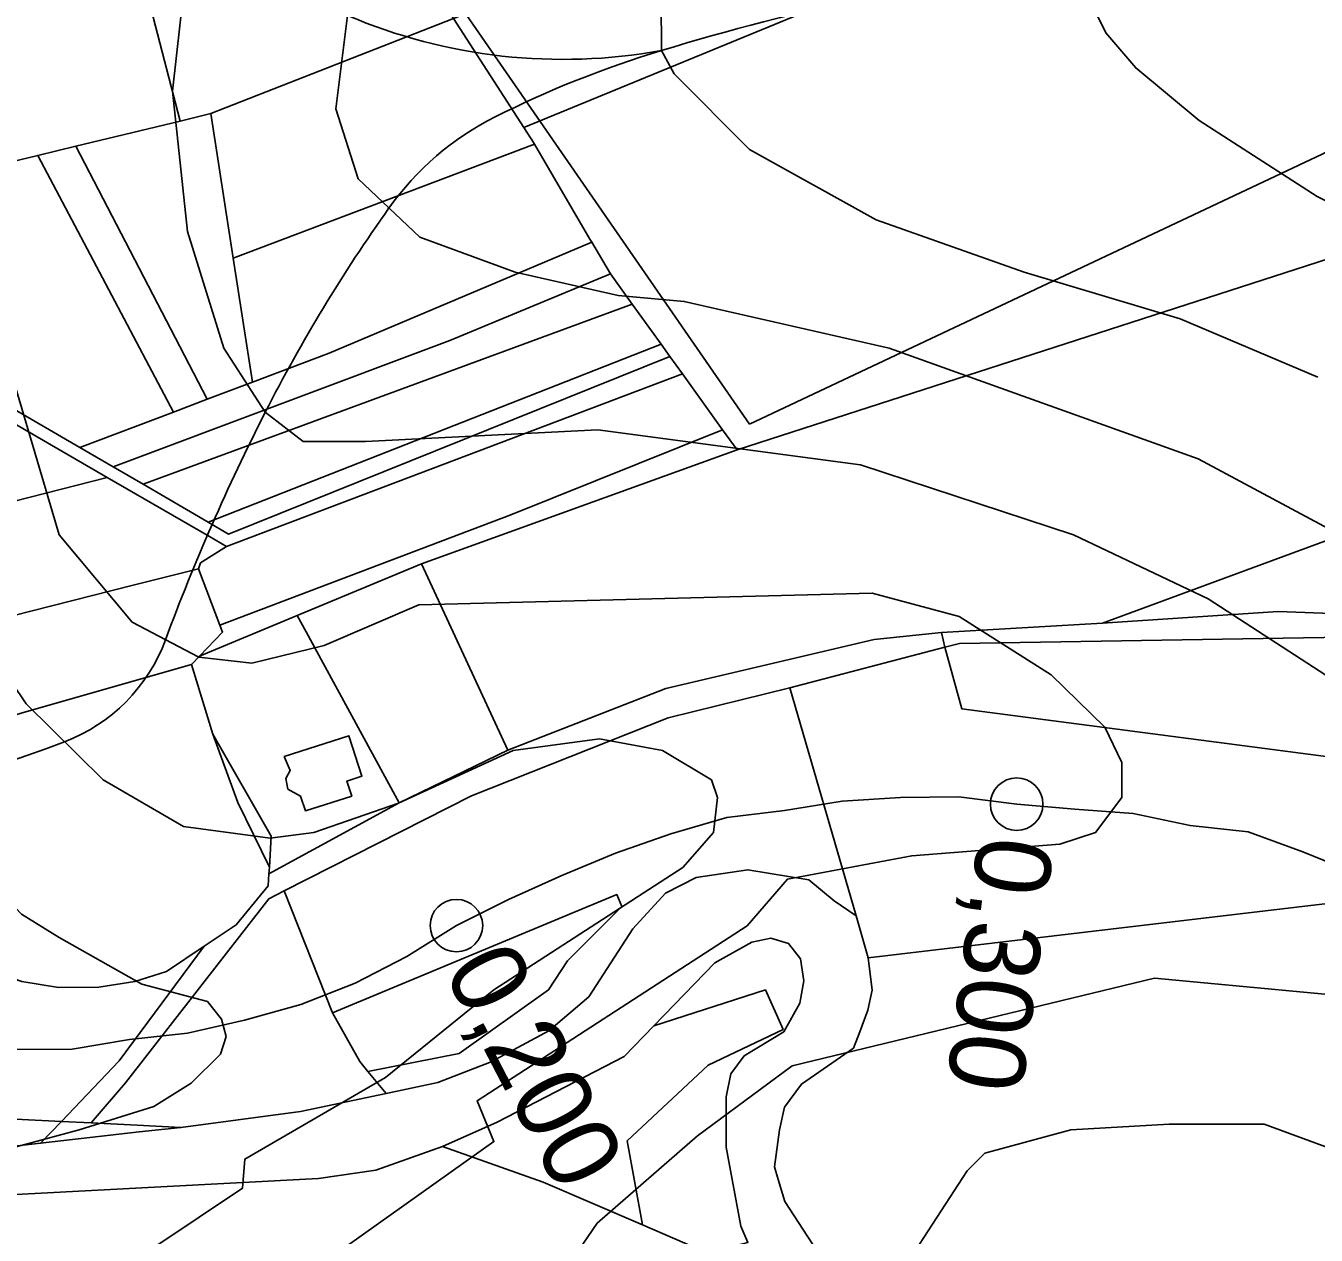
# Model space of a CAD drawing. Extents: x -510989 to -501240, y -1184665 to -1176098.
# Drawn here: x -509352 to -509130.9, y -1179477 to -1179269.8 of the extents above; entities that cross this region are included whole.
import ezdxf

# ---------------------------------------------------------------- set-up
doc = ezdxf.new("R2010")
doc.units = 0
for name, color, linetype in [('NAVRH_rozvodnice', 7, 'Continuous'), ('orna_puda', 7, 'Continuous'), ('ostatni_plocha_x_manipulacni_plocha', 7, 'Continuous'), ('ostatni_plocha_x_neplodna_puda', 7, 'Continuous'), ('ostatni_plocha_x_ostatni_komunikace', 7, 'Continuous'), ('ostatni_plocha_x_silnice', 7, 'Continuous'), ('STAV_systematicke_odvodneni', 7, 'Continuous'), ('trasovani_toku', 7, 'Continuous'), ('trvaly_travni_porost', 7, 'Continuous'), ('vodni_plocha_x_zamokrena_plocha', 7, 'Continuous'), ('vrstevnice_01', 7, 'Continuous'), ('vrstevnice_02', 7, 'Continuous'), ('zahrada', 7, 'Continuous'), ('zastavena_plocha_a_nadvori', 7, 'Continuous')]:
    doc.layers.add(name, color=color, linetype=linetype)

msp = doc.modelspace()

# ---------------------------------------------------------------- linework, layer by layer
at = {"layer": 'NAVRH_rozvodnice'}
for centre, radius, start, end in [((-509121.63, -1179673.51), 417.56, 96.9373, 106.9113), ((-509260, -1179181.33), 94.2, 246.9349, 280.341), ((-509190.44, -1179447.18), 181.01, 106.9113, 116.6322), ((-509249.32, -1179329.77), 49.66, 116.6322, 144.5973), ((-509061.79, -1179463.05), 279.73, 144.5973, 152.9866), ((-508984.09, -1179502.67), 366.95, 152.9866, 159.64), ((-509356.13, -1179364.6), 29.89, 291.0285, 339.64), ((-509414.25, -1179213.41), 191.87, 258.3329, 291.0285), ((-509229.64, -1179301.75), 244.6, 204.0197, 246.4643)]:
    msp.add_arc(centre, radius, start, end, dxfattribs=at)
at = {"layer": 'orna_puda'}
for points in [[(-509076.81, -1179197.19), (-509210.24, -1179254.85), (-509207.03, -1179262.64), (-509266.7, -1179287.2), (-509278.76, -1179268.53), (-509180.65, -1179229.56), (-509081.74, -1179187.06)], [(-509292.36, -1179257.49), (-509286.98, -1179255.81), (-509278.76, -1179268.53), (-509320.36, -1179284.83), (-509325.57, -1179286.09), (-509330.63, -1179266.76), (-509326.53, -1179266.76), (-509307.98, -1179262.36)], [(-509320.36, -1179284.83), (-509278.76, -1179268.53), (-509266.7, -1179287.2), (-509264.93, -1179289.94), (-509264.87, -1179290.04), (-509316.49, -1179309.62)], [(-509264.87, -1179290.04), (-509255.35, -1179306.33), (-509255.04, -1179306.86), (-509300.06, -1179325.87), (-509313.18, -1179330.83), (-509316.49, -1179309.62)], [(-509255.04, -1179306.86), (-509251.86, -1179312.29), (-509279.35, -1179323.71), (-509337.05, -1179345.38), (-509342.8, -1179342.04), (-509326.75, -1179335.97), (-509320.94, -1179333.77), (-509313.18, -1179330.83), (-509300.06, -1179325.87)], [(-509251.86, -1179312.29), (-509248.12, -1179317.48), (-509331.95, -1179348.35), (-509337.05, -1179345.38), (-509279.35, -1179323.71)], [(-509248.12, -1179317.48), (-509243.17, -1179324.34), (-509320.81, -1179354.82), (-509331.95, -1179348.35)], [(-509239.5, -1179329.43), (-509232.61, -1179338.99), (-509268.93, -1179353.6), (-509318.79, -1179372.47), (-509322.43, -1179362.81), (-509322.09, -1179361.81), (-509317.63, -1179359.01)], [(-509250.74, -1179418.66), (-509249.88, -1179420.73), (-509259.22, -1179430.01), (-509262.44, -1179435.01), (-509277.78, -1179445.9), (-509293.43, -1179448.96), (-509294.82, -1179447.27), (-509299.51, -1179438.92)], [(-509244.42, -1179441.17), (-509225.29, -1179435), (-509222.26, -1179441.78), (-509235.07, -1179447.92), (-509248.95, -1179460.87), (-509246.37, -1179475.26), (-509263.39, -1179467.95), (-509280.62, -1179461.86), (-509271.28, -1179457.69), (-509249.49, -1179446.42)]]:
    msp.add_lwpolyline(points, close=True, dxfattribs=at)
msp.add_lwpolyline([(-509096.81, -1179299.39), (-509230.1, -1179342.45), (-509232.61, -1179338.99), (-509239.5, -1179329.43), (-509241.64, -1179326.46), (-509243.17, -1179324.34), (-509248.12, -1179317.48), (-509251.86, -1179312.29), (-509255.04, -1179306.86), (-509255.35, -1179306.33), (-509264.87, -1179290.04), (-509264.93, -1179289.94), (-509266.7, -1179287.2), (-509207.03, -1179262.64), (-509210.24, -1179254.85), (-509076.81, -1179197.19)], dxfattribs=at)
at = {"layer": 'ostatni_plocha_x_manipulacni_plocha'}
for points in [[(-509284.22, -1179362), (-509269.44, -1179393.92), (-509288.08, -1179402.95), (-509301.07, -1179379.03), (-509304, -1179373.63), (-509305.51, -1179370.84)], [(-509305.51, -1179370.84), (-509304, -1179373.63), (-509301.07, -1179379.03), (-509288.08, -1179402.95), (-509310.37, -1179415.09), (-509310.3, -1179413.94), (-509309.98, -1179408.66), (-509320.02, -1179391.16), (-509323.65, -1179379.22), (-509322.28, -1179377.8)], [(-509320.02, -1179391.16), (-509309.98, -1179408.66), (-509310.3, -1179413.94), (-509315.71, -1179402.9)], [(-509307.77, -1179394.99), (-509306.72, -1179397.4), (-509307.49, -1179398.79), (-509307.11, -1179400.57), (-509304.94, -1179401.79), (-509304.13, -1179404.31), (-509296.19, -1179401.77), (-509297.01, -1179399.2), (-509294.44, -1179398.37), (-509296.66, -1179391.44)], [(-509367.47, -1179426.62), (-509357.46, -1179430.05), (-509357.1, -1179432.06), (-509352.71, -1179433.56), (-509346.44, -1179434.6), (-509339.56, -1179434.54), (-509333.34, -1179433.54), (-509327.93, -1179431.87), (-509321.45, -1179427.53), (-509336.03, -1179447.17), (-509345.95, -1179457.53), (-509361.74, -1179456.77), (-509362.16, -1179452.72), (-509360.92, -1179452.7), (-509354.81, -1179452.62), (-509354.89, -1179447.24), (-509354.92, -1179445.17), (-509358.59, -1179432.54), (-509361.5, -1179429.63), (-509366.25, -1179427.89), (-509367.37, -1179427.48)], [(-509224.33, -1179426.12), (-509221.31, -1179427.02), (-509219.26, -1179429.7), (-509218.7, -1179433.42), (-509219.38, -1179437.3), (-509222.1, -1179442.16), (-509228.9, -1179446.3), (-509231.18, -1179449.41), (-509231.98, -1179453.34), (-509231.99, -1179461.98), (-509229.51, -1179475.49), (-509228.28, -1179478.29), (-509235.24, -1179480.05), (-509246.37, -1179475.26), (-509248.95, -1179460.87), (-509235.07, -1179447.92), (-509222.26, -1179441.78), (-509225.29, -1179435), (-509244.42, -1179441.17), (-509233.94, -1179430.34), (-509227.6, -1179426.81)], [(-509345.95, -1179457.53), (-509349.53, -1179461.27), (-509366.43, -1179463.21), (-509383.93, -1179465.38), (-509391.81, -1179464.7), (-509397.83, -1179462.93), (-509401.32, -1179461.12), (-509404.1, -1179458.33), (-509400.34, -1179458.29), (-509395.73, -1179462), (-509391.16, -1179463.21), (-509390.99, -1179461.48), (-509382.86, -1179462.27), (-509379.84, -1179458.92), (-509373.07, -1179459.94), (-509361.54, -1179458.76), (-509361.74, -1179456.77)], [(-509340.86, -1179457.78), (-509332.96, -1179458.16), (-509325.47, -1179458.59), (-509332.63, -1179459.34), (-509349.53, -1179461.27), (-509345.95, -1179457.53)]]:
    msp.add_lwpolyline(points, close=True, dxfattribs=at)
at = {"layer": 'ostatni_plocha_x_neplodna_puda'}
for points in [[(-509232.61, -1179338.99), (-509230.1, -1179342.45), (-509284.22, -1179362), (-509305.51, -1179370.84), (-509322.28, -1179377.8), (-509318.32, -1179373.69), (-509318.79, -1179372.47), (-509268.93, -1179353.6)], [(-509110.64, -1179351.17), (-509067.16, -1179352.61), (-509072.25, -1179357.15), (-509083.67, -1179365.13), (-509102.55, -1179371.49), (-509137.38, -1179370.15), (-509167.51, -1179372.13)], [(-509094.91, -1179374.01), (-509094.69, -1179399.52), (-509191.61, -1179386.85), (-509194.51, -1179376.28), (-509192, -1179375.62)]]:
    msp.add_lwpolyline(points, close=True, dxfattribs=at)
msp.add_lwpolyline([(-509360.79, -1179477.49), (-509360.83, -1179475.33), (-509358.84, -1179474.32), (-509358.81, -1179473.38), (-509359.4, -1179472.4), (-509360.89, -1179472.2), (-509361.37, -1179470.48), (-509329.98, -1179468.83), (-509301.88, -1179467.35), (-509292.06, -1179465.9), (-509280.62, -1179461.86), (-509263.39, -1179467.95), (-509246.37, -1179475.26), (-509235.24, -1179480.05)], dxfattribs=at)
at = {"layer": 'ostatni_plocha_x_ostatni_komunikace'}
for points in [[(-509404.18, -1179303.47), (-509399.56, -1179303.43), (-509398.12, -1179304.81), (-509383.51, -1179308.94), (-509370.93, -1179321.28), (-509354.95, -1179334.98), (-509342.8, -1179342.04), (-509337.05, -1179345.38), (-509331.95, -1179348.35), (-509320.81, -1179354.82), (-509317.29, -1179356.87), (-509241.64, -1179326.46), (-509239.5, -1179329.43), (-509317.63, -1179359.01), (-509320.57, -1179357.31), (-509338.08, -1179347.17), (-509354.32, -1179337.76), (-509358.69, -1179334.22), (-509369.88, -1179325.14), (-509378.6, -1179318.06), (-509378.65, -1179318.01), (-509384.73, -1179313.61), (-509395.33, -1179308.26), (-509401.56, -1179305.12)], [(-509243.17, -1179324.34), (-509241.64, -1179326.46), (-509317.29, -1179356.87), (-509320.81, -1179354.82)], [(-509206.62, -1179374.96), (-509195.12, -1179373.77), (-509194.51, -1179376.28), (-509221.07, -1179383.22), (-509241.96, -1179388.37), (-509275.63, -1179401.72), (-509307.75, -1179418.02), (-509310.41, -1179419.38), (-509334.98, -1179450.92), (-509340.86, -1179457.78), (-509345.95, -1179457.53), (-509336.03, -1179447.17), (-509321.45, -1179427.53), (-509315.98, -1179423.87), (-509310.5, -1179417.16), (-509310.37, -1179415.09), (-509288.08, -1179402.95), (-509269.44, -1179393.92), (-509242.33, -1179383.33)]]:
    msp.add_lwpolyline(points, close=True, dxfattribs=at)
msp.add_lwpolyline([(-509094.91, -1179374.01), (-509192, -1179375.62), (-509194.51, -1179376.28), (-509195.12, -1179373.77), (-509167.51, -1179372.13), (-509137.38, -1179370.15), (-509102.55, -1179371.49)], dxfattribs=at)
at = {"layer": 'ostatni_plocha_x_silnice'}
for points in [[(-509366.43, -1179463.21), (-509349.53, -1179461.27), (-509332.63, -1179459.34), (-509325.47, -1179458.59), (-509304.99, -1179455.84), (-509290.31, -1179452.73), (-509281.42, -1179450.86), (-509272.27, -1179447.34), (-509262.38, -1179442.04), (-509255.55, -1179436.19), (-509248, -1179424.52), (-509242.43, -1179418.45), (-509237.14, -1179415.74), (-509228.29, -1179414.41), (-509217.86, -1179416.14), (-509213.49, -1179419.71), (-509209.73, -1179422.33), (-509207.65, -1179429.48), (-509206.99, -1179435.04), (-509207.7, -1179438.47), (-509209.12, -1179442.17), (-509210.19, -1179444.96), (-509219.11, -1179451.13), (-509222.02, -1179455.07), (-509222.84, -1179458.99), (-509223.72, -1179465.32), (-509223.08, -1179467.47), (-509221.97, -1179471.24), (-509202.14, -1179501.69)], [(-509228.28, -1179478.29), (-509229.51, -1179475.49), (-509231.99, -1179461.98), (-509231.98, -1179453.34), (-509231.18, -1179449.41), (-509228.9, -1179446.3), (-509222.1, -1179442.16), (-509219.38, -1179437.3), (-509218.7, -1179433.42), (-509219.26, -1179429.7), (-509221.31, -1179427.02), (-509224.33, -1179426.12), (-509227.6, -1179426.81), (-509233.94, -1179430.34), (-509244.42, -1179441.17), (-509249.49, -1179446.42), (-509271.28, -1179457.69), (-509280.62, -1179461.86), (-509292.06, -1179465.9), (-509301.88, -1179467.35), (-509329.98, -1179468.83), (-509361.37, -1179470.48)]]:
    msp.add_lwpolyline(points, dxfattribs=at)
at = {"layer": 'STAV_systematicke_odvodneni'}
for p, q in [((-509228.03, -1179338.07), (-509023.75, -1179241.74)), ((-509288.68, -1179250.26), (-509228.03, -1179338.07))]:
    msp.add_line(p, q, dxfattribs=at)
at = {"layer": 'trasovani_toku'}
for p, q in [((-509212.11, -1179402.67), (-509202.13, -1179402.04)), ((-509202.13, -1179402.04), (-509192.13, -1179401.91)), ((-509192.13, -1179401.91), (-509182.21, -1179403.17)), ((-509231.9, -1179405.48), (-509221.98, -1179404.27)), ((-509221.98, -1179404.27), (-509212.11, -1179402.67)), ((-509182.21, -1179403.17), (-509172.25, -1179404.05)), ((-509172.25, -1179404.05), (-509162.27, -1179404.78)), ((-509241.5, -1179408.28), (-509231.9, -1179405.48)), ((-509162.27, -1179404.78), (-509152.49, -1179406.84)), ((-509152.49, -1179406.84), (-509142.54, -1179407.9)), ((-509250.95, -1179411.55), (-509241.5, -1179408.28)), ((-509142.54, -1179407.9), (-509133.15, -1179411.34)), ((-509260.19, -1179415.38), (-509250.95, -1179411.55)), ((-509133.15, -1179411.34), (-509123.9, -1179415.13)), ((-509269.29, -1179419.52), (-509260.19, -1179415.38)), ((-509278.24, -1179423.98), (-509269.29, -1179419.52)), ((-509286.72, -1179429.28), (-509278.24, -1179423.98)), ((-509295.62, -1179433.85), (-509286.72, -1179429.28)), ((-509304.93, -1179437.51), (-509295.62, -1179433.85)), ((-509314.56, -1179440.21), (-509304.93, -1179437.51)), ((-509324.31, -1179442.41), (-509314.56, -1179440.21)), ((-509344.11, -1179445.17), (-509334.25, -1179443.48)), ((-509334.25, -1179443.48), (-509324.31, -1179442.41)), ((-509354.11, -1179445.22), (-509344.11, -1179445.17))]:
    msp.add_line(p, q, dxfattribs=at)
for centre in [(-509182.21, -1179403.17), (-509278.24, -1179423.98)]:
    msp.add_circle(centre, 4.5, dxfattribs=at)
at = {"layer": 'trvaly_travni_porost'}
for points in [[(-508978.56, -1179251.27), (-508978.81, -1179257.56), (-508989.24, -1179271.89), (-509002.08, -1179283.15), (-509013.85, -1179296.97), (-509031.08, -1179317.2), (-509067.16, -1179352.61), (-509110.64, -1179351.17), (-509167.51, -1179372.13), (-509195.12, -1179373.77), (-509206.62, -1179374.96), (-509242.33, -1179383.33), (-509269.44, -1179393.92), (-509284.22, -1179362), (-509230.1, -1179342.45), (-509096.81, -1179299.39), (-509029.73, -1179275.57), (-509015.7, -1179267.23), (-508972.56, -1179241.6)], [(-509241.96, -1179388.37), (-509221.07, -1179383.22), (-509209.73, -1179422.33), (-509213.49, -1179419.71), (-509217.86, -1179416.14), (-509228.29, -1179414.41), (-509237.14, -1179415.74), (-509242.43, -1179418.45), (-509248, -1179424.52), (-509255.55, -1179436.19), (-509262.38, -1179442.04), (-509272.27, -1179447.34), (-509281.42, -1179450.86), (-509290.31, -1179452.73), (-509293.43, -1179448.96), (-509277.78, -1179445.9), (-509262.44, -1179435.01), (-509259.22, -1179430.01), (-509249.88, -1179420.73), (-509250.74, -1179418.66), (-509299.51, -1179438.92), (-509307.75, -1179418.02), (-509275.63, -1179401.72)], [(-509310.41, -1179419.38), (-509307.75, -1179418.02), (-509299.51, -1179438.92), (-509294.82, -1179447.27), (-509293.43, -1179448.96), (-509290.31, -1179452.73), (-509304.99, -1179455.84), (-509325.47, -1179458.59), (-509332.96, -1179458.16), (-509340.86, -1179457.78), (-509334.98, -1179450.92)]]:
    msp.add_lwpolyline(points, close=True, dxfattribs=at)
msp.add_lwpolyline([(-509202.14, -1179501.69), (-509221.97, -1179471.24), (-509223.08, -1179467.47), (-509223.72, -1179465.32), (-509222.84, -1179458.99), (-509222.02, -1179455.07), (-509219.11, -1179451.13), (-509210.19, -1179444.96), (-509209.12, -1179442.17), (-509207.7, -1179438.47), (-509206.99, -1179435.04), (-509207.65, -1179429.48), (-509128.96, -1179420.22)], dxfattribs=at)
at = {"layer": 'vodni_plocha_x_zamokrena_plocha'}
msp.add_lwpolyline([(-509194.51, -1179376.28), (-509191.61, -1179386.85), (-509094.69, -1179399.52), (-509040.27, -1179388.32), (-509037.37, -1179394.43), (-509056.26, -1179404.79), (-509077.25, -1179414.3), (-509128.96, -1179420.22), (-509207.65, -1179429.48), (-509209.73, -1179422.33), (-509221.07, -1179383.22)], close=True, dxfattribs=at)
at = {"layer": 'vrstevnice_01'}
for points in [[(-509060.31, -1179009), (-509071.5, -1179024), (-509079.59, -1179045), (-509086.59, -1179089), (-509093.69, -1179117), (-509110.31, -1179158), (-509122.31, -1179180), (-509129.81, -1179192), (-509157.19, -1179220), (-509167.09, -1179232), (-509170.91, -1179239), (-509172.81, -1179256), (-509171.31, -1179262), (-509166.91, -1179271), (-509161.81, -1179277), (-509150.91, -1179286), (-509130.69, -1179299), (-509096.5, -1179316), (-509068.5, -1179334), (-509054.69, -1179340), (-509043.5, -1179340), (-509029.19, -1179336), (-509018.5, -1179331)], [(-509128.69, -1179356), (-509151.09, -1179344), (-509204.09, -1179325), (-509239.19, -1179317), (-509250.5, -1179316), (-509268.19, -1179312), (-509284.5, -1179306), (-509295.09, -1179296), (-509298.91, -1179284), (-509296.91, -1179268), (-509290.09, -1179253), (-509283.41, -1179243), (-509270.81, -1179232), (-509216.91, -1179201), (-509202.5, -1179190), (-509181.59, -1179170), (-509157.5, -1179139), (-509138.41, -1179107), (-509130.09, -1179086)], [(-509307, -1179486), (-509271.81, -1179461), (-509274.69, -1179454), (-509228.41, -1179424), (-509221.5, -1179416), (-509200.19, -1179412), (-509174.81, -1179410), (-509168.69, -1179408), (-509164.19, -1179402), (-509164.19, -1179396), (-509167.09, -1179390), (-509176.31, -1179381), (-509192.09, -1179371), (-509207, -1179367), (-509284.69, -1179369), (-509300.91, -1179376), (-509313.31, -1179379), (-509322.41, -1179378), (-509333.81, -1179372), (-509346.31, -1179357), (-509366.81, -1179288), (-509369, -1179262)], [(-509367.59, -1179478), (-509365, -1179475), (-509364.31, -1179466), (-509361.59, -1179464), (-509342.91, -1179459), (-509330.09, -1179455), (-509323.69, -1179451), (-509318.69, -1179446), (-509317.69, -1179443), (-509318.5, -1179440), (-509320.91, -1179437), (-509332.19, -1179434), (-509346.31, -1179426), (-509352.81, -1179422), (-509367.09, -1179407), (-509376.31, -1179394), (-509380.81, -1179383), (-509386.59, -1179356), (-509392.09, -1179344), (-509399.81, -1179332), (-509405.81, -1179319), (-509413.31, -1179264)], [(-509206.31, -1179490), (-509190.69, -1179466), (-509187.69, -1179463), (-509172.91, -1179459), (-509156.09, -1179458), (-509139.81, -1179458), (-509115.41, -1179467), (-509089.41, -1179471), (-509074.81, -1179470), (-509013.31, -1179459)]]:
    msp.add_lwpolyline(points, dxfattribs=at)
at = {"layer": 'vrstevnice_02'}
for points in [[(-509098.5, -1179401), (-509149.41, -1179368), (-509172.5, -1179357), (-509209, -1179345), (-509254, -1179339), (-509293.81, -1179341), (-509304.5, -1179341), (-509311, -1179336), (-509318.09, -1179325), (-509324.31, -1179305), (-509326.91, -1179281), (-509324.31, -1179258), (-509320.09, -1179247), (-509311.31, -1179234), (-509293.31, -1179217), (-509239.19, -1179194), (-509230.5, -1179189), (-509199, -1179160), (-509175, -1179127), (-509164, -1179107), (-509158.91, -1179094), (-509157.31, -1179075), (-509157.81, -1179030), (-509161.31, -1179006)], [(-509221.81, -1179231), (-509235.81, -1179244), (-509243.19, -1179257), (-509243.09, -1179274), (-509240.91, -1179278), (-509228, -1179291), (-509206.31, -1179303), (-509180.91, -1179312), (-509154.19, -1179320), (-509130.59, -1179330)], [(-509390.5, -1179246), (-509389.91, -1179270), (-509387.41, -1179286), (-509380.5, -1179304), (-509376.09, -1179331), (-509359.41, -1179375), (-509352, -1179386), (-509338.81, -1179399), (-509325, -1179407), (-509310.19, -1179409), (-509302.69, -1179408), (-509288.19, -1179403), (-509268.5, -1179394), (-509253.69, -1179392), (-509242.91, -1179394), (-509234.5, -1179399), (-509233.5, -1179402), (-509234.19, -1179408), (-509239.41, -1179414), (-509271.81, -1179435), (-509290.41, -1179450), (-509314.5, -1179464), (-509314.91, -1179469), (-509344.81, -1179489)], [(-509272.59, -1179502), (-509254.09, -1179475), (-509236.91, -1179460), (-509220.69, -1179448), (-509158.59, -1179433), (-509116, -1179437)]]:
    msp.add_lwpolyline(points, dxfattribs=at)
at = {"layer": 'zahrada'}
for points in [[(-509347.44, -1179266.76), (-509330.63, -1179266.76), (-509325.57, -1179286.09), (-509343.47, -1179290.41), (-509349.99, -1179291.98), (-509377.1, -1179298.52), (-509384.09, -1179272), (-509361.83, -1179267.12), (-509354.63, -1179265.94)], [(-509325.57, -1179286.09), (-509320.36, -1179284.83), (-509316.49, -1179309.62), (-509313.18, -1179330.83), (-509320.94, -1179333.77), (-509343.47, -1179290.41)], [(-509349.99, -1179291.98), (-509343.47, -1179290.41), (-509320.94, -1179333.77), (-509326.75, -1179335.97)], [(-509377.1, -1179298.52), (-509349.99, -1179291.98), (-509326.75, -1179335.97), (-509342.8, -1179342.04), (-509354.95, -1179334.98), (-509370.93, -1179321.28), (-509383.51, -1179308.94), (-509398.12, -1179304.81), (-509399.56, -1179303.43), (-509398.88, -1179303.42), (-509394.58, -1179302.74)], [(-509358.69, -1179334.22), (-509354.32, -1179337.76), (-509338.08, -1179347.17), (-509359.41, -1179352.6), (-509362.23, -1179353.32), (-509369.98, -1179355.29), (-509372.72, -1179355.99), (-509376.79, -1179338.43), (-509366.9, -1179336.13)], [(-509359.41, -1179352.6), (-509338.08, -1179347.17), (-509320.57, -1179357.31), (-509317.63, -1179359.01), (-509322.09, -1179361.81), (-509322.43, -1179362.81), (-509333.89, -1179365.71), (-509354.32, -1179370.89), (-509357.13, -1179371.6), (-509357.47, -1179371.68), (-509365.32, -1179373.73), (-509369.98, -1179355.29), (-509362.23, -1179353.32)], [(-509333.89, -1179365.71), (-509322.43, -1179362.81), (-509318.79, -1179372.47), (-509318.32, -1179373.69), (-509322.28, -1179377.8), (-509323.65, -1179379.22), (-509352.68, -1179387.54), (-509353.02, -1179387.64), (-509371.31, -1179392.88), (-509383.39, -1179394.17), (-509379.39, -1179377.4), (-509365.32, -1179373.73), (-509357.47, -1179371.68), (-509357.13, -1179371.6), (-509354.32, -1179370.89)], [(-509352.68, -1179387.54), (-509323.65, -1179379.22), (-509320.02, -1179391.16), (-509315.71, -1179402.9), (-509310.3, -1179413.94), (-509310.37, -1179415.09), (-509310.5, -1179417.16), (-509315.98, -1179423.87), (-509321.45, -1179427.53), (-509327.93, -1179431.87), (-509333.34, -1179433.54), (-509339.56, -1179434.54), (-509346.44, -1179434.6), (-509352.71, -1179433.56), (-509357.1, -1179432.06), (-509357.46, -1179430.05), (-509367.47, -1179426.62), (-509371.31, -1179392.88), (-509353.02, -1179387.64)]]:
    msp.add_lwpolyline(points, close=True, dxfattribs=at)
at = {"layer": 'zastavena_plocha_a_nadvori'}
msp.add_lwpolyline([(-509307.77, -1179394.99), (-509296.66, -1179391.44), (-509294.44, -1179398.37), (-509297.01, -1179399.2), (-509296.19, -1179401.77), (-509304.13, -1179404.31), (-509304.94, -1179401.79), (-509307.11, -1179400.57), (-509307.49, -1179398.79), (-509306.72, -1179397.4)], close=True, dxfattribs=at)

# ---------------------------------------------------------------- texts
at = {"layer": 'trasovani_toku'}
for s, rotation, p in [('0,300', 262.6766, (-509188.7, -1179408.23)), ('0,200', 297.4646, (-509280.61, -1179431.61))]:
    msp.add_text(s, height=13, rotation=rotation, dxfattribs=at).set_placement(p)

doc.saveas('drawing.dxf')
